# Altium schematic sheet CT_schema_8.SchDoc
size 278 x 170 mm
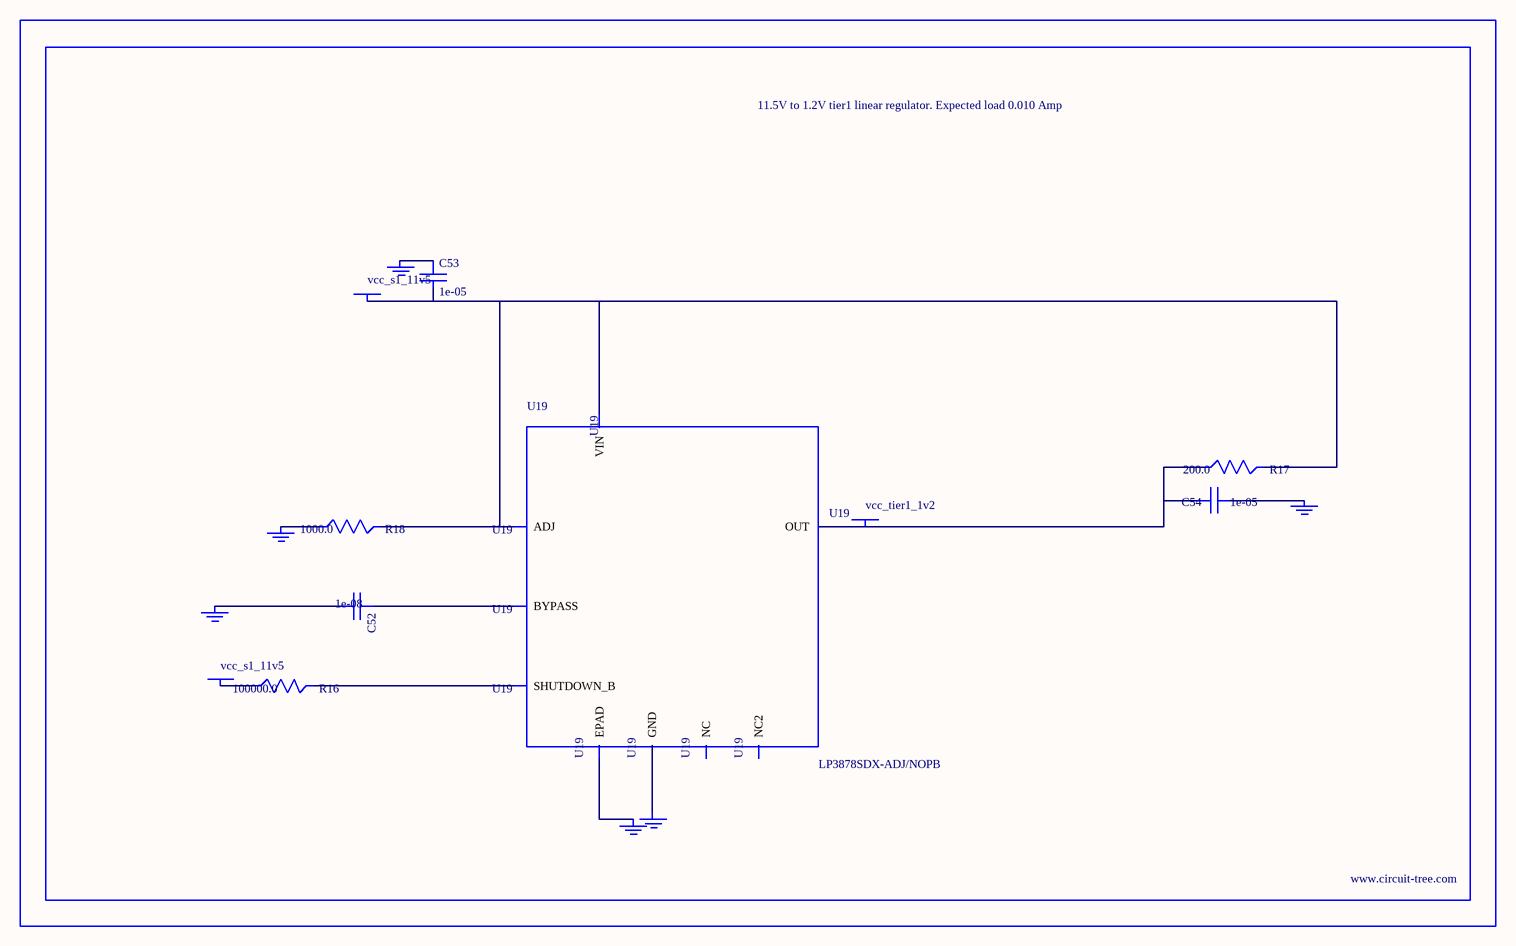
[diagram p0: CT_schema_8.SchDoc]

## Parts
BORDER7  (no value)
C52  1e-08  [C0402]
C53  1e-05  [C1210]
C54  1e-05  [C0805]
GND_INSTANCE_7_0  (no value)
GND_INSTANCE_7_1  (no value)
GND_INSTANCE_7_2  (no value)
GND_INSTANCE_7_3  (no value)
GND_INSTANCE_7_4  (no value)
GND_INSTANCE_7_5  (no value)
POWER_INSTANCE_7_0  vcc_s1_11v5
POWER_INSTANCE_7_1  vcc_s1_11v5
POWER_INSTANCE_7_2  vcc_tier1_1v2
R16  100000.0  [R0603]
R17  200.0  [R0603]
R18  1000.0  [R0603]
U19  LP3878SDX-ADJ/NOPB  [WSON-8]

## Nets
NetC52_1: C52.1 U19.1(BYPASS)
NetC52_2: C52.2 GND_INSTANCE_7_0.0(GND)
NetC53_1: C53.1 GND_INSTANCE_7_1.0(GND)
NetC53_2: C53.2 POWER_INSTANCE_7_0.0(PWR) R17.2 R18.2 U19.4(VIN) U19.6(ADJ)
NetC54_1: C54.1 GND_INSTANCE_7_2.0(GND)
NetC54_2: C54.2 POWER_INSTANCE_7_2.0(PWR) R17.1 U19.5(OUT)
NetGND_INSTANCE_7_3_0: GND_INSTANCE_7_3.0(GND) R18.1
NetGND_INSTANCE_7_4_0: GND_INSTANCE_7_4.0(GND) U19.PAD(EPAD)
NetGND_INSTANCE_7_5_0: GND_INSTANCE_7_5.0(GND) U19.3(GND)
NetPOWER_INSTANCE_7_1_0: POWER_INSTANCE_7_1.0(PWR) R16.1
NetR16_2: R16.2 U19.8(SHUTDOWN_B)

Not connected (* = marked no-connect by the designer): U19 2(NC) 7(NC2)

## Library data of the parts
BORDER7 = BORDER_PAGE7
C52 = C0402C103K3RAC
C53 = C1210C106K5PACTU
C54 = GRM219R60J106ME19D
GND_INSTANCE_7_0-GND_INSTANCE_7_5 = GND
POWER_INSTANCE_7_0-POWER_INSTANCE_7_2 = PWR
R16 = RC0603JR-07100KL
R17 = RC0603JR-07200RL
R18 = RC0603JR-071KL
